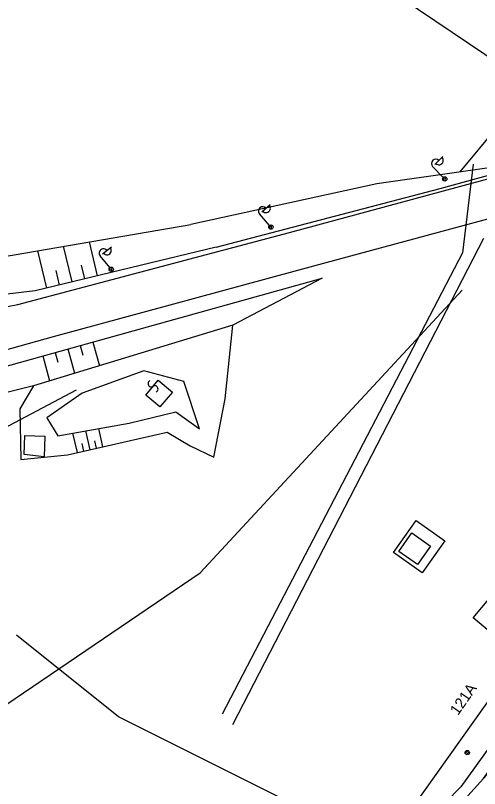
# Model space of a CAD drawing. Extents: x -469926 to -462499, y -1098642 to -1092733.
# Drawn here: x -465808.8 to -465755.3, y -1095836.3 to -1095747.3 of the extents above; entities that cross this region are included whole.
import ezdxf

# ---------------------------------------------------------------- set-up
doc = ezdxf.new("R2010")
doc.units = 0
for name, color, linetype in [('Vrstva 1', 7, 'Continuous'), ('Vrstva 10', 7, 'Continuous'), ('Vrstva 11', 7, 'Continuous'), ('Vrstva 12', 7, 'Continuous'), ('Vrstva 13', 7, 'Continuous'), ('Vrstva 4', 7, 'Continuous'), ('Vrstva 48', 7, 'Continuous'), ('Vrstva 50', 7, 'Continuous'), ('Vrstva 51', 7, 'Continuous'), ('Vrstva 55', 7, 'Continuous'), ('Vrstva 62', 7, 'Continuous')]:
    doc.layers.add(name, color=color, linetype=linetype)

msp = doc.modelspace()

# ---------------------------------------------------------------- linework, layer by layer
at = {"layer": 'Vrstva 1'}
msp.add_line((-465788.8, -1095874.65), (-465635.97, -1095660.09), dxfattribs=at)
for points in [[(-465775.781, -1095858.01), (-465766.01, -1095847.458), (-465754.867, -1095835.14), (-465745.127, -1095821.621)], [(-465766.01, -1095847.458), (-465754.867, -1095835.14), (-465743.694, -1095822.788)]]:
    msp.add_lwpolyline(points, dxfattribs=at)
at = {"layer": 'Vrstva 10'}
msp.add_line((-465801.792, -1095790.428), (-465903.302, -1095844.471), dxfattribs=at)
msp.add_lwpolyline([(-465733.373, -1095850.251), (-465752.461, -1095850.251), (-465796.905, -1095828.029), (-465808.645, -1095818.637)], dxfattribs=at)
at = {"layer": 'Vrstva 12'}
for p, q in [((-465787.505, -1095811.451), (-465757.31, -1095778.92)), ((-465825.529, -1095837.251), (-465787.505, -1095811.451))]:
    msp.add_line(p, q, dxfattribs=at)
msp.add_lwpolyline([(-465807.774, -1095797.86), (-465807.709, -1095795.66), (-465805.377, -1095795.755), (-465805.479, -1095798.113)], close=True, dxfattribs=at)
at = {"layer": 'Vrstva 13'}
for points in [[(-465838.428, -1095771.566), (-465834.57, -1095778.174), (-465829.935, -1095781.442), (-465824.938, -1095782.605), (-465818.606, -1095782.506), (-465808.495, -1095780.589), (-465777.214, -1095772.3), (-465751.524, -1095765.336), (-465742.5, -1095763.978), (-465735.021, -1095764.484), (-465728.964, -1095766.278), (-465722.487, -1095769.872)], [(-465725.124, -1095773.69), (-465731.083, -1095770.643), (-465737.306, -1095768.943), (-465744.388, -1095768.752), (-465753.392, -1095770.491), (-465774.436, -1095776.17), (-465804.42, -1095784.289), (-465857.81, -1095799.241), (-465876.937, -1095806.252), (-465888.375, -1095812.085), (-465898.457, -1095818.323), (-465902.347, -1095822), (-465903.923, -1095826.471), (-465903.648, -1095830.838), (-465902.613, -1095834.901), (-465899.413, -1095840.431), (-465874.372, -1095879.591), (-465865.495, -1095894.209)]]:
    msp.add_lwpolyline(points, dxfattribs=at)
at = {"layer": 'Vrstva 4'}
for p, q in [((-465793.76, -1095791.01), (-465792.34, -1095789.29)), ((-465792.34, -1095789.29), (-465790.7, -1095790.67)), ((-465790.7, -1095790.67), (-465792.13, -1095792.38)), ((-465792.13, -1095792.38), (-465793.76, -1095791.01))]:
    msp.add_line(p, q, dxfattribs=at)
at = {"layer": 'Vrstva 48'}
for points in [[(-465802.231, -1095777.993), (-465803.224, -1095773.889)], [(-465799.315, -1095777.287), (-465800.259, -1095773.385)], [(-465805.147, -1095778.698), (-465806.188, -1095774.394)], [(-465800.773, -1095777.64), (-465801.161, -1095776.039)], [(-465803.689, -1095778.346), (-465804.096, -1095776.664)], [(-465801.299, -1095785.302), (-465800.993, -1095786.407)], [(-465799.853, -1095784.902), (-465799.098, -1095787.629)], [(-465804.19, -1095786.103), (-465803.876, -1095787.235)], [(-465802.745, -1095785.702), (-465801.97, -1095788.499)], [(-465805.636, -1095786.503), (-465804.842, -1095789.368)], [(-465800.17, -1095797.295), (-465800.666, -1095795.115)], [(-465798.707, -1095796.962), (-465799.187, -1095794.852)], [(-465801.632, -1095797.628), (-465802.144, -1095795.378)], [(-465800.901, -1095797.461), (-465801.103, -1095796.575)], [(-465799.438, -1095797.128), (-465799.634, -1095796.27)]]:
    msp.add_lwpolyline(points, dxfattribs=at)
at = {"layer": 'Vrstva 50'}
for p, q in [((-465757.57, -1095765.332), (-465684.425, -1095676.798)), ((-465756.074, -1095764.415), (-465757.295, -1095774.625)), ((-465757.295, -1095774.625), (-465784.983, -1095827.719))]:
    msp.add_line(p, q, dxfattribs=at)
at = {"layer": 'Vrstva 51'}
msp.add_line((-465754.852, -1095772.991), (-465783.762, -1095828.944), dxfattribs=at)
for centre, radius, start, end in [((-465793.126, -1095789.681), 0.376, 115.50036, 301.81149), ((-465792.725, -1095790.319), 0.377, 294.82432, 122.48753)]:
    msp.add_arc(centre, radius, start, end, dxfattribs=at)
at = {"layer": 'Vrstva 55'}
for p, q in [((-465760.471, -1095764.454), (-465759.534, -1095763.553)), ((-465759.51, -1095765.958), (-465760.723, -1095764.697)), ((-465759.458, -1095766.357), (-465759.449, -1095765.916)), ((-465759.27, -1095766.379), (-465759.261, -1095765.899)), ((-465780.406, -1095769.933), (-465779.427, -1095769.077)), ((-465779.517, -1095771.481), (-465780.669, -1095770.163)), ((-465779.484, -1095771.882), (-465779.455, -1095771.442)), ((-465779.298, -1095771.912), (-465779.266, -1095771.434)), ((-465798.736, -1095774.762), (-465797.728, -1095773.941)), ((-465797.902, -1095776.34), (-465799.008, -1095774.983)), ((-465797.883, -1095776.742), (-465797.839, -1095776.304)), ((-465797.698, -1095776.779), (-465797.65, -1095776.302)), ((-465756.968, -1095832.244), (-465756.644, -1095831.921)), ((-465756.838, -1095832.379), (-465756.51, -1095832.052))]:
    msp.add_line(p, q, dxfattribs=at)
for points in [[(-465609.888, -1095625.282), (-465638.963, -1095671.505), (-465681.941, -1095731.193), (-465731.933, -1095800.622), (-465757.477, -1095836.099), (-465808.227, -1095887.932), (-465849.014, -1095921.297)], [(-465777.86, -1095736.176), (-465714.07, -1095779.117)], [(-465785.648, -1095773.98), (-465806.492, -1095779.024), (-465822.973, -1095780.964), (-465824.505, -1095775.538), (-465834.047, -1095769.358), (-465840.334, -1095762.243), (-465833.754, -1095757.203), (-465820.092, -1095746.977), (-465802.851, -1095736.61), (-465825.584, -1095754.484), (-465835.689, -1095762.764), (-465829.286, -1095769.192), (-465818.461, -1095771.239), (-465814.095, -1095775.738), (-465788.561, -1095771.396)], [(-465838.428, -1095771.566), (-465834.57, -1095778.174), (-465829.935, -1095781.442), (-465824.938, -1095782.605), (-465818.606, -1095782.506), (-465808.495, -1095780.589), (-465777.214, -1095772.3), (-465751.524, -1095765.336), (-465742.5, -1095763.978), (-465735.021, -1095764.484), (-465728.964, -1095766.278), (-465722.487, -1095769.872)], [(-465785.648, -1095773.98), (-465759.87, -1095767.225), (-465747.992, -1095763.955), (-465767.148, -1095766.706), (-465788.561, -1095771.396)], [(-465785.932, -1095798.147), (-465784.624, -1095791.439), (-465783.738, -1095782.976)], [(-465787.561, -1095794.884), (-465789.383, -1095789.43), (-465793.98, -1095788.215), (-465801.094, -1095790.781), (-465805.16, -1095793.612), (-465803.893, -1095795.688), (-465795.66, -1095794.225), (-465790.306, -1095792.919), (-465787.561, -1095794.884)], [(-465806.688, -1095789.927), (-465808.26, -1095792.584), (-465808.147, -1095798.411), (-465802.785, -1095797.89), (-465791.304, -1095795.278), (-465788.632, -1095796.87), (-465785.932, -1095798.147)], [(-465765.222, -1095809.142), (-465762.629, -1095805.464), (-465759.339, -1095807.783), (-465761.932, -1095811.461), (-465765.222, -1095809.142)], [(-465764.615, -1095809.008), (-465763.112, -1095806.869), (-465760.96, -1095808.382), (-465762.464, -1095810.521), (-465764.615, -1095809.008)], [(-465756.048, -1095816.638), (-465753.075, -1095813.072), (-465751.241, -1095814.595), (-465754.217, -1095818.165), (-465756.048, -1095816.638)]]:
    msp.add_lwpolyline(points, dxfattribs=at)
for points in [[(-465861.31, -1095822.129), (-465874.998, -1095825.73), (-465885.421, -1095824.756), (-465891.154, -1095819.248), (-465889.132, -1095815.87), (-465878.184, -1095808.977), (-465866.236, -1095806.407), (-465848.456, -1095799.773), (-465835.884, -1095795.481), (-465815.374, -1095789.199), (-465785.149, -1095780.831), (-465773.453, -1095777.552), (-465783.738, -1095782.976), (-465806.688, -1095789.927), (-465830.188, -1095795.809), (-465849.903, -1095803.838), (-465871.602, -1095811.334), (-465887.799, -1095818.935), (-465885.433, -1095822.542), (-465873.885, -1095822.373)], [(-465807.774, -1095797.86), (-465807.709, -1095795.66), (-465805.377, -1095795.755), (-465805.479, -1095798.113)]]:
    msp.add_lwpolyline(points, close=True, dxfattribs=at)
for centre in [(-465759.336, -1095766.138), (-465759.336, -1095766.138), (-465779.352, -1095771.669), (-465779.352, -1095771.669), (-465797.744, -1095776.534), (-465797.744, -1095776.534), (-465756.737, -1095832.152)]:
    msp.add_circle(centre, 0.25, dxfattribs=at)
for centre, start, end in [((-465760.363, -1095764.35), 43.90609, 223.90609), ((-465759.998, -1095764.008), 223.20351, 44.60866), ((-465780.292, -1095769.834), 41.17832, 221.17832), ((-465779.912, -1095769.51), 220.47574, 41.88089), ((-465798.62, -1095774.668), 39.17662, 219.17662), ((-465798.228, -1095774.357), 218.47405, 39.87919)]:
    msp.add_arc(centre, 0.5, start, end, dxfattribs=at)
at = {"layer": 'Vrstva 62'}
for points in [[(-465785.648, -1095773.98), (-465806.492, -1095779.024), (-465822.973, -1095780.964), (-465824.505, -1095775.538), (-465834.047, -1095769.358), (-465840.334, -1095762.243), (-465833.754, -1095757.203), (-465820.092, -1095746.977), (-465802.851, -1095736.61), (-465825.584, -1095754.484), (-465835.689, -1095762.764), (-465829.286, -1095769.192), (-465818.461, -1095771.239), (-465814.095, -1095775.738), (-465788.561, -1095771.396)], [(-465785.648, -1095773.98), (-465759.87, -1095767.225), (-465747.992, -1095763.955), (-465767.148, -1095766.706), (-465788.561, -1095771.396)], [(-465802.231, -1095777.993), (-465803.224, -1095773.889)], [(-465799.315, -1095777.287), (-465800.259, -1095773.385)], [(-465805.147, -1095778.698), (-465806.188, -1095774.394)], [(-465800.773, -1095777.64), (-465801.161, -1095776.039)], [(-465803.689, -1095778.346), (-465804.096, -1095776.664)], [(-465801.299, -1095785.302), (-465800.993, -1095786.407)], [(-465799.853, -1095784.902), (-465799.098, -1095787.629)], [(-465804.19, -1095786.103), (-465803.876, -1095787.235)], [(-465802.745, -1095785.702), (-465801.97, -1095788.499)], [(-465805.636, -1095786.503), (-465804.842, -1095789.368)]]:
    msp.add_lwpolyline(points, dxfattribs=at)
msp.add_lwpolyline([(-465861.31, -1095822.129), (-465874.998, -1095825.73), (-465885.421, -1095824.756), (-465891.154, -1095819.248), (-465889.132, -1095815.87), (-465878.184, -1095808.977), (-465866.236, -1095806.407), (-465848.456, -1095799.773), (-465835.884, -1095795.481), (-465815.374, -1095789.199), (-465785.149, -1095780.831), (-465773.453, -1095777.552), (-465783.738, -1095782.976), (-465806.688, -1095789.927), (-465830.188, -1095795.809), (-465849.903, -1095803.838), (-465871.602, -1095811.334), (-465887.799, -1095818.935), (-465885.433, -1095822.542), (-465873.885, -1095822.373)], close=True, dxfattribs=at)

# ---------------------------------------------------------------- texts
at = {"layer": 'Vrstva 11'}
msp.add_text('121A', height=1.25, rotation=55.1125, dxfattribs=at).set_placement((-465757.809, -1095827.952))

doc.saveas('drawing.dxf')
